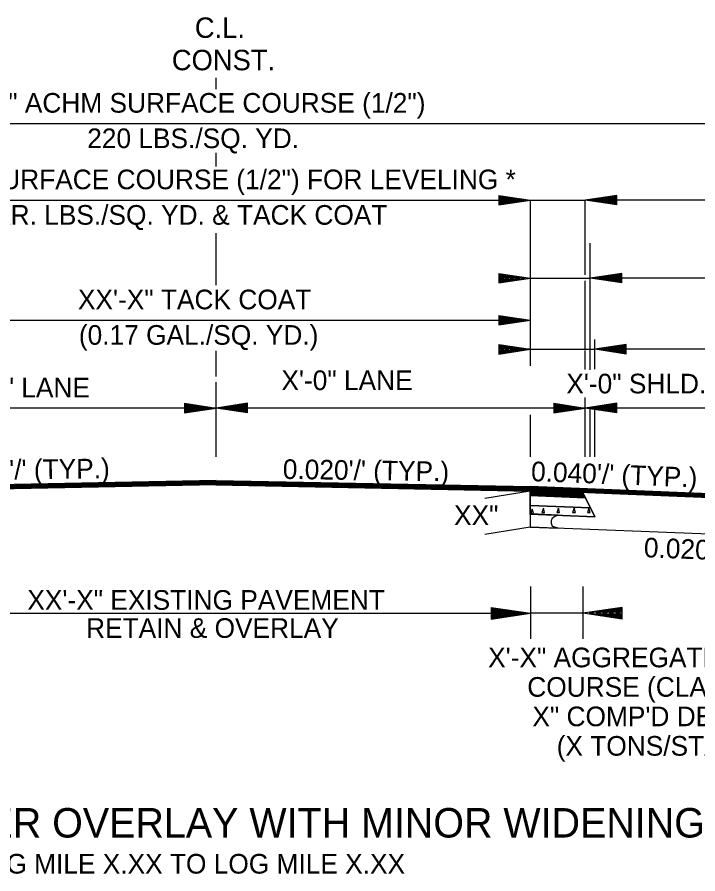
# Model space of a CAD drawing. Extents: x 544199 to 1930787, y -1968972 to 596640.
# Drawn here: x 551844.7 to 552104.5, y -1957268.6 to -1956941.5 of the extents above; entities that cross this region are included whole.
import ezdxf

# ---------------------------------------------------------------- set-up
doc = ezdxf.new("R2010")
doc.units = 0
doc.layers.add('R_Draft', color=7, linetype='Continuous')

msp = doc.modelspace()

# ---------------------------------------------------------------- linework, layer by layer
at = {"layer": 'R_Draft'}
for p, q in [((551920.64, -1956969.07), (551920.64, -1956964.66)), ((551720.38, -1956982.17), (552120.83, -1956982.17)), ((551920.64, -1956998.59), (551920.64, -1956993.36)), ((552028.57, -1957009.61), (552040.57, -1957011.41)), ((552028.57, -1957009.61), (552028.57, -1957013.21)), ((552028.57, -1957009.91), (552038.56, -1957011.41)), ((552028.57, -1957010.21), (552036.5, -1957011.41)), ((552028.57, -1957010.51), (552034.5, -1957011.41)), ((552028.57, -1957010.83), (552032.47, -1957011.41)), ((552073.54, -1957009.61), (552061.54, -1957011.41)), ((552073.54, -1957009.91), (552063.54, -1957011.41)), ((552073.54, -1957010.21), (552065.61, -1957011.41)), ((552073.54, -1957010.51), (552067.61, -1957011.41)), ((552073.54, -1957010.82), (552069.64, -1957011.41)), ((552073.54, -1957013.21), (552073.54, -1957009.61)), ((551800.64, -1957011.41), (552040.57, -1957011.41)), ((552028.57, -1957011.13), (552030.46, -1957011.41)), ((552028.57, -1957013.21), (552040.57, -1957011.41)), ((552028.57, -1957012), (552032.47, -1957011.41)), ((552028.57, -1957012.6), (552036.5, -1957011.41)), ((552028.57, -1957012.91), (552038.56, -1957011.41)), ((552028.57, -1957012.3), (552034.5, -1957011.41)), ((552028.57, -1957011.69), (552030.46, -1957011.41)), ((552040.57, -1957074.63), (552040.57, -1957011.41)), ((552040.57, -1957011.41), (552061.54, -1957011.41)), ((552073.54, -1957013.21), (552061.54, -1957011.41)), ((552061.54, -1957039.89), (552061.54, -1957011.41)), ((552346.45, -1957011.41), (552061.54, -1957011.41)), ((552073.54, -1957012.91), (552063.54, -1957011.41)), ((552073.54, -1957012.6), (552065.61, -1957011.41)), ((552073.54, -1957012.3), (552067.61, -1957011.41)), ((552073.54, -1957011.99), (552069.64, -1957011.41)), ((552073.54, -1957011.13), (552071.64, -1957011.41)), ((552073.54, -1957011.69), (552071.64, -1957011.41)), ((551920.64, -1957043.82), (551920.64, -1957024.05)), ((552063.46, -1957068.01), (552063.46, -1957027.88)), ((552028.57, -1957039.43), (552040.57, -1957041.23)), ((552028.57, -1957039.43), (552028.57, -1957043.03)), ((552028.57, -1957039.73), (552038.56, -1957041.23)), ((552028.57, -1957040.04), (552036.5, -1957041.23)), ((552028.57, -1957040.34), (552034.5, -1957041.23)), ((552075.46, -1957039.43), (552063.46, -1957041.23)), ((552075.46, -1957039.73), (552065.46, -1957041.23)), ((552075.46, -1957040.04), (552067.52, -1957041.23)), ((552075.46, -1957040.34), (552069.52, -1957041.23)), ((552075.46, -1957043.03), (552075.46, -1957039.43)), ((552028.57, -1957040.65), (552032.47, -1957041.23)), ((552028.57, -1957040.95), (552030.46, -1957041.23)), ((552028.57, -1957043.03), (552040.57, -1957041.23)), ((552028.57, -1957041.82), (552032.47, -1957041.23)), ((552028.57, -1957042.42), (552036.5, -1957041.23)), ((552028.57, -1957042.73), (552038.56, -1957041.23)), ((552028.57, -1957042.12), (552034.5, -1957041.23)), ((552028.57, -1957041.51), (552030.46, -1957041.23)), ((552040.57, -1957041.23), (552063.46, -1957041.23)), ((552061.54, -1957068.06), (552061.54, -1957042.23)), ((552075.46, -1957043.03), (552063.46, -1957041.23)), ((552348.37, -1957041.23), (552063.46, -1957041.23)), ((552075.46, -1957042.73), (552065.46, -1957041.23)), ((552075.46, -1957042.42), (552067.52, -1957041.23)), ((552075.46, -1957042.12), (552069.52, -1957041.23)), ((552075.46, -1957040.64), (552071.56, -1957041.23)), ((552075.46, -1957041.81), (552071.56, -1957041.23)), ((552075.46, -1957040.95), (552073.56, -1957041.23)), ((552075.46, -1957041.51), (552073.56, -1957041.23)), ((552028.57, -1957055.43), (552040.57, -1957057.23)), ((552028.57, -1957055.43), (552028.57, -1957059.03)), ((552028.57, -1957055.73), (552038.56, -1957057.23)), ((552028.57, -1957056.04), (552036.5, -1957057.23)), ((552028.57, -1957056.34), (552034.5, -1957057.23)), ((552028.57, -1957056.65), (552032.47, -1957057.23)), ((551800.64, -1957057.23), (552040.57, -1957057.23)), ((552028.57, -1957056.95), (552030.46, -1957057.23)), ((552028.57, -1957059.03), (552040.57, -1957057.23)), ((552028.57, -1957057.82), (552032.47, -1957057.23)), ((552028.57, -1957058.43), (552036.5, -1957057.23)), ((552028.57, -1957058.73), (552038.56, -1957057.23)), ((552028.57, -1957058.13), (552034.5, -1957057.23)), ((552028.57, -1957057.51), (552030.46, -1957057.23)), ((552028.57, -1957066.56), (552040.57, -1957068.36)), ((552028.57, -1957066.56), (552028.57, -1957070.16)), ((552065.16, -1957075.96), (552065.16, -1957064.58)), ((552077.16, -1957066.56), (552065.16, -1957068.36)), ((552077.16, -1957070.16), (552077.16, -1957066.56)), ((551920.64, -1957078.75), (551920.64, -1957068.88)), ((552028.57, -1957066.86), (552038.56, -1957068.36)), ((552028.57, -1957067.16), (552036.5, -1957068.36)), ((552028.57, -1957067.46), (552034.5, -1957068.36)), ((552028.57, -1957067.78), (552032.47, -1957068.36)), ((552028.57, -1957068.08), (552030.46, -1957068.36)), ((552028.57, -1957070.16), (552040.57, -1957068.36)), ((552028.57, -1957068.95), (552032.47, -1957068.36)), ((552028.57, -1957069.55), (552036.5, -1957068.36)), ((552028.57, -1957069.86), (552038.56, -1957068.36)), ((552028.57, -1957069.25), (552034.5, -1957068.36)), ((552028.57, -1957068.64), (552030.46, -1957068.36)), ((552040.57, -1957068.36), (552034.6, -1957068.36)), ((552040.57, -1957068.36), (552065.16, -1957068.36)), ((552061.54, -1957076.08), (552061.54, -1957068.78)), ((552063.46, -1957076.25), (552063.46, -1957068.71)), ((552077.16, -1957070.16), (552065.16, -1957068.36)), ((552348.37, -1957068.36), (552065.16, -1957068.36)), ((552077.16, -1957066.86), (552067.16, -1957068.36)), ((552077.16, -1957069.86), (552067.16, -1957068.36)), ((552077.16, -1957067.16), (552069.22, -1957068.36)), ((552077.16, -1957069.55), (552069.22, -1957068.36)), ((552077.16, -1957067.46), (552071.22, -1957068.36)), ((552077.16, -1957069.25), (552071.22, -1957068.36)), ((552077.16, -1957067.77), (552073.26, -1957068.36)), ((552077.16, -1957068.94), (552073.26, -1957068.36)), ((552077.16, -1957068.08), (552075.26, -1957068.36)), ((552077.16, -1957068.64), (552075.26, -1957068.36)), ((551920.64, -1957109.43), (551920.64, -1957080.88)), ((551908.64, -1957088.97), (551920.64, -1957090.77)), ((551908.64, -1957088.97), (551908.64, -1957092.57)), ((551908.64, -1957089.27), (551918.64, -1957090.77)), ((551932.64, -1957088.97), (551920.64, -1957090.77)), ((551932.64, -1957089.27), (551922.65, -1957090.77)), ((551932.64, -1957092.57), (551932.64, -1957088.97)), ((552049.54, -1957088.97), (552061.54, -1957090.77)), ((552049.54, -1957088.97), (552049.54, -1957092.57)), ((552049.54, -1957089.27), (552059.54, -1957090.77)), ((552061.54, -1957109.43), (552061.54, -1957086.78)), ((552073.54, -1957088.97), (552061.54, -1957090.77)), ((552073.54, -1957089.27), (552063.54, -1957090.77)), ((552073.54, -1957092.57), (552073.54, -1957088.97)), ((551920.64, -1957090.77), (551779.67, -1957090.77)), ((551908.64, -1957089.58), (551916.57, -1957090.77)), ((551908.64, -1957089.88), (551914.58, -1957090.77)), ((551908.64, -1957090.19), (551912.54, -1957090.77)), ((551908.64, -1957090.49), (551910.54, -1957090.77)), ((551908.64, -1957092.57), (551920.64, -1957090.77)), ((551908.64, -1957091.36), (551912.54, -1957090.77)), ((551908.64, -1957091.96), (551916.57, -1957090.77)), ((551908.64, -1957092.27), (551918.64, -1957090.77)), ((551908.64, -1957091.66), (551914.58, -1957090.77)), ((551908.64, -1957091.05), (551910.54, -1957090.77)), ((552061.54, -1957090.77), (551920.64, -1957090.77)), ((551932.64, -1957092.57), (551920.64, -1957090.77)), ((551932.64, -1957092.27), (551922.65, -1957090.77)), ((551932.64, -1957089.58), (551924.71, -1957090.77)), ((551932.64, -1957091.96), (551924.71, -1957090.77)), ((551932.64, -1957089.88), (551926.71, -1957090.77)), ((551932.64, -1957091.66), (551926.71, -1957090.77)), ((551932.64, -1957090.18), (551928.74, -1957090.77)), ((551932.64, -1957091.35), (551928.74, -1957090.77)), ((551932.64, -1957090.49), (551930.75, -1957090.77)), ((551932.64, -1957091.05), (551930.75, -1957090.77)), ((552049.54, -1957089.58), (552057.47, -1957090.77)), ((552049.54, -1957089.88), (552055.47, -1957090.77)), ((552049.54, -1957090.19), (552053.44, -1957090.77)), ((552049.54, -1957090.49), (552051.44, -1957090.77)), ((552049.54, -1957092.57), (552061.54, -1957090.77)), ((552049.54, -1957091.36), (552053.44, -1957090.77)), ((552049.54, -1957091.96), (552057.47, -1957090.77)), ((552049.54, -1957092.27), (552059.54, -1957090.77)), ((552049.54, -1957091.66), (552055.47, -1957090.77)), ((552049.54, -1957091.05), (552051.44, -1957090.77)), ((552120.83, -1957090.77), (552061.54, -1957090.77)), ((552073.54, -1957092.57), (552061.54, -1957090.77)), ((552063.46, -1957109.43), (552063.46, -1957091.11)), ((552073.54, -1957092.27), (552063.54, -1957090.77)), ((552065.16, -1957109.43), (552065.16, -1957091.34)), ((552073.54, -1957089.58), (552065.61, -1957090.77)), ((552073.54, -1957091.96), (552065.61, -1957090.77)), ((552073.54, -1957089.88), (552067.61, -1957090.77)), ((552073.54, -1957091.66), (552067.61, -1957090.77)), ((552073.54, -1957090.18), (552069.64, -1957090.77)), ((552073.54, -1957091.35), (552069.64, -1957090.77)), ((552073.54, -1957090.49), (552071.64, -1957090.77)), ((552073.54, -1957091.05), (552071.64, -1957090.77)), ((552040.64, -1957109.43), (552040.64, -1957093.39)), ((551920.64, -1957118.38), (551800.64, -1957120.78)), ((551920.65, -1957118.67), (551800.65, -1957121.07)), ((551920.65, -1957118.97), (551800.65, -1957121.37)), ((551920.63, -1957118.97), (552040.63, -1957121.37)), ((551920.64, -1957118.38), (552040.64, -1957120.78)), ((551920.64, -1957118.67), (552040.64, -1957121.07)), ((551920.66, -1957119.27), (551800.66, -1957121.67)), ((551920.67, -1957119.57), (551800.67, -1957121.97)), ((551920.67, -1957119.87), (551800.67, -1957122.27)), ((551920.68, -1957120.07), (551800.68, -1957122.47)), ((551920.61, -1957119.87), (552040.61, -1957122.27)), ((551920.61, -1957120.07), (552040.61, -1957122.47)), ((551920.62, -1957119.27), (552040.62, -1957121.67)), ((551920.62, -1957119.57), (552040.62, -1957121.97)), ((552120.9, -1957125.19), (552040.59, -1957121.97)), ((552120.9, -1957124.89), (552040.61, -1957121.67)), ((552120.9, -1957124.59), (552040.62, -1957121.37)), ((552120.9, -1957124.29), (552040.63, -1957121.07)), ((552120.9, -1957123.99), (552040.64, -1957120.78)), ((552040.51, -1957122.47), (552023.21, -1957125.35)), ((552040.51, -1957128.27), (552040.51, -1957122.47)), ((552060.67, -1957123.28), (552040.51, -1957122.47)), ((552040.51, -1957122.47), (552040.51, -1957136.23)), ((552060.82, -1957123.58), (552040.51, -1957122.77)), ((552060.98, -1957123.89), (552040.51, -1957123.07)), ((552061.13, -1957124.2), (552040.51, -1957123.37)), ((552061.28, -1957124.5), (552040.51, -1957123.67)), ((552061.44, -1957124.81), (552040.51, -1957123.97)), ((552061.54, -1957125.01), (552040.51, -1957124.17)), ((552120.9, -1957125.49), (552040.58, -1957122.27)), ((552060.57, -1957123.07), (552065.16, -1957132.25)), ((552043.53, -1957131.35), (552040.51, -1957131.23)), ((552040.51, -1957131.23), (552065.16, -1957132.25)), ((552051.09, -1957131.65), (552043.53, -1957131.35)), ((552040.51, -1957136.23), (552023.21, -1957139.11)), ((552242.98, -1957144.33), (552040.51, -1957136.23)), ((552040.57, -1957158.87), (552040.57, -1957178.87)), ((552060.57, -1957158.87), (552060.57, -1957178.87)), ((552025.57, -1957166.87), (552040.57, -1957169.12)), ((552025.57, -1957166.87), (552025.57, -1957171.37)), ((552025.57, -1957167.24), (552038.06, -1957169.12)), ((552025.57, -1957167.62), (552035.48, -1957169.12)), ((552025.57, -1957168), (552032.99, -1957169.12)), ((552075.57, -1957166.87), (552060.57, -1957169.12)), ((552075.57, -1957167.24), (552063.07, -1957169.12)), ((552075.57, -1957167.62), (552065.65, -1957169.12)), ((552075.57, -1957168), (552068.15, -1957169.12)), ((552075.57, -1957171.37), (552075.57, -1957166.87)), ((551800.64, -1957169.12), (552040.57, -1957169.12)), ((552025.57, -1957168.39), (552030.44, -1957169.12)), ((552025.57, -1957168.76), (552027.94, -1957169.12)), ((552025.57, -1957171.37), (552040.57, -1957169.12)), ((552025.57, -1957169.85), (552030.44, -1957169.12)), ((552025.57, -1957170.61), (552035.48, -1957169.12)), ((552025.57, -1957170.99), (552038.06, -1957169.12)), ((552025.57, -1957170.23), (552032.99, -1957169.12)), ((552025.57, -1957169.47), (552027.94, -1957169.12)), ((552060.57, -1957169.12), (552040.57, -1957169.12)), ((552075.57, -1957171.37), (552060.57, -1957169.12)), ((552075.57, -1957170.99), (552063.07, -1957169.12)), ((552075.57, -1957170.61), (552065.65, -1957169.12)), ((552075.57, -1957170.23), (552068.15, -1957169.12)), ((552075.57, -1957168.38), (552070.69, -1957169.12)), ((552075.57, -1957169.84), (552070.69, -1957169.12)), ((552075.57, -1957168.76), (552073.2, -1957169.12)), ((552075.57, -1957169.47), (552073.2, -1957169.12))]:
    msp.add_line(p, q, dxfattribs=at)
for points in [[(552040.51, -1957124.17), (552061.54, -1957125.01), (552063.46, -1957128.85), (552040.51, -1957127.93)], [(552040.51, -1957127.93), (552063.46, -1957128.85), (552065.16, -1957132.25), (552040.51, -1957131.23)]]:
    msp.add_lwpolyline(points, close=True, dxfattribs=at)
for points in [[(552040.51, -1957131.23), (552040.51, -1957136.23), (552051.24, -1957136.66)], [(552041.32, -1957129.32), (552040.71, -1957130.98), (552041.81, -1957130.93), (552041.32, -1957129.32)], [(552045.54, -1957129.03), (552044.93, -1957130.69), (552046.03, -1957130.65), (552045.54, -1957129.03)], [(552051.24, -1957136.66), (552049.07, -1957135.94), (552048.65, -1957134.9), (552048.66, -1957133.67), (552049.05, -1957132.73), (552049.91, -1957132.06), (552051.09, -1957131.65)], [(552051.26, -1957129.03), (552050.65, -1957130.69), (552051.75, -1957130.65), (552051.26, -1957129.03)], [(552057.31, -1957129.03), (552056.7, -1957130.69), (552057.8, -1957130.65), (552057.31, -1957129.03)], [(552062.93, -1957129.03), (552062.32, -1957130.69), (552063.42, -1957130.65), (552062.93, -1957129.03)]]:
    msp.add_lwpolyline(points, dxfattribs=at)

# ---------------------------------------------------------------- texts
for s, height, p in [('C.L.', 7.8, (551912.54, -1956949.46)), ('CONST.', 7.8, (551903.76, -1956961.82)), ('XX\'-X" ACHM SURFACE COURSE (1/2")', 7.5, (551815.99, -1956978.01)), ('220 LBS./SQ. YD. ', 7.5, (551871.47, -1956991.55)), ('XX\'-X" ACHM SURFACE COURSE (1/2") FOR LEVELING *', 7.5, (551767.97, -1957007.24)), ('VAR. LBS./SQ. YD. & TACK COAT', 7.5, (551828.86, -1957020.79)), ('XX\'-X" TACK COAT', 7.5, (551867.92, -1957053.07)), ('(0.17 GAL./SQ. YD.)', 7.5, (551868.28, -1957066.61)), ('X\'-0" LANE', 7.5, (551945.58, -1957083.91)), ('X\'-0" LANE', 7.5, (551822.44, -1957086.71)), ('X\'-0" SHLD.', 7.5, (552054.3, -1957085.18)), ('XX"', 7.5, (552011.45, -1957135.44)), ('XX\'-X" EXISTING PAVEMENT', 7.5, (551848.62, -1957167.79)), ('RETAIN & OVERLAY', 7.5, (551871.03, -1957178.52)), ('X\'-X" AGGREGATE BASE', 7.5, (552024.46, -1957189.74)), ('COURSE (CLASS 7)', 7.5, (552039.4, -1957200.99)), ('X" COMP\'D DEPTH', 7.5, (552041.35, -1957212.24)), ('(X TONS/STA.)', 7.5, (552050.62, -1957223.49)), ('2 LANE OPEN SHOULDER OVERLAY WITH MINOR WIDENING', 11.25, (551667.49, -1957254.73)), ('LOG MILE X.XX TO LOG MILE X.XX', 7.5, (551827.23, -1957268.5))]:
    msp.add_text(s, height=height, dxfattribs=at).set_placement(p)
for s, rotation, p in [("0.020'/' (TYP.)", 0.8719, (551816.66, -1957118.47)), ("0.020'/' (TYP.)", 359.164, (551946.06, -1957117.82)), ("0.040'/' (TYP.) ", 357.8168, (552040.73, -1957118.65)), ("0.020'/' ", 357.8168, (552083.79, -1957147.72))]:
    msp.add_text(s, height=7.5, rotation=rotation, dxfattribs=at).set_placement(p)

doc.saveas('drawing.dxf')
